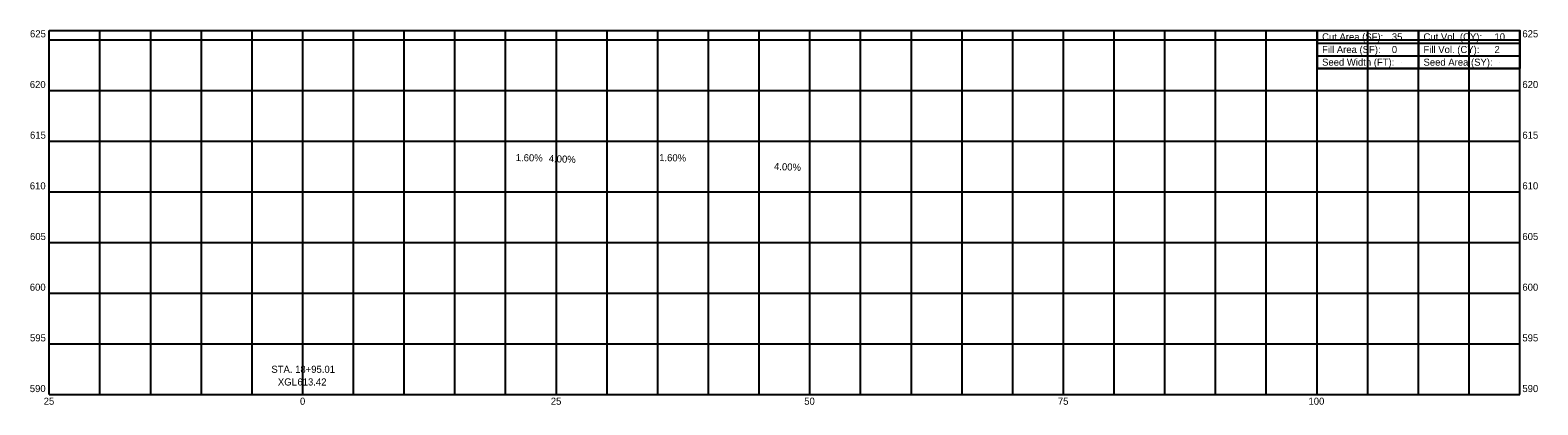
# Model space of a CAD drawing. Extents: x -27 to 122, y 589 to 626.
import ezdxf

# ---------------------------------------------------------------- set-up
doc = ezdxf.new("R2010")
doc.units = 0
for name, color, linetype in [('Default', 7, 'Continuous'), ('SH_Data', 7, 'Continuous'), ('SH_Major_Grid_Line', 7, 'Continuous'), ('SH_Masking', 7, 'Continuous'), ('SH_Text', 7, 'Continuous')]:
    doc.layers.add(name, color=color, linetype=linetype)

msp = doc.modelspace()

# ---------------------------------------------------------------- linework, layer by layer
at = {"layer": 'Default'}
msp.add_circle((120, 625.92), 0.000417, dxfattribs=at)
msp.add_circle((120, 625.92), 0.000417, dxfattribs=at)
msp.add_circle((120, 625.92), 0.000417, dxfattribs=at)
msp.add_circle((120, 625.92), 0.000417, dxfattribs=at)
msp.add_circle((120, 625.92), 0.000417, dxfattribs=at)
msp.add_circle((120, 625.92), 0.000417, dxfattribs=at)
msp.add_circle((120, 625.92), 0.000417, dxfattribs=at)
msp.add_circle((120, 625.92), 0.000417, dxfattribs=at)
msp.add_circle((120, 625.92), 0.000417, dxfattribs=at)
msp.add_circle((120, 625.92), 0.000417, dxfattribs=at)
msp.add_circle((120, 625.92), 0.000417, dxfattribs=at)
msp.add_circle((120, 625.92), 0.000417, dxfattribs=at)
at = {"layer": 'SH_Data'}
for p, q in [((100, 625.92), (120, 625.92)), ((100, 625.92), (100, 623.42)), ((110, 625.92), (110, 622.17)), ((120, 625.92), (120, 623.42)), ((100, 624.67), (120, 624.67)), ((100, 623.42), (120, 623.42)), ((108.3, 622.8), (108.3, 622.8)), ((117.95, 622.8), (117.95, 622.8))]:
    msp.add_line(p, q, dxfattribs=at)
msp.add_lwpolyline([(100, 623.42), (100, 622.17), (120, 622.17), (120, 623.42)], dxfattribs=at)
at = {"layer": 'SH_Major_Grid_Line'}
for p, q in [((-25, 625.92), (120, 625.92)), ((-25, 590), (-25, 625.92)), ((-20, 590), (-20, 625.92)), ((-15, 590), (-15, 625.92)), ((-10, 590), (-10, 625.92)), ((-5, 590), (-5, 625.92)), ((0, 590), (0, 625.92)), ((5, 590), (5, 625.92)), ((10, 590), (10, 625.92)), ((15, 590), (15, 625.92)), ((20, 590), (20, 625.92)), ((25, 590), (25, 625.92)), ((30, 590), (30, 625.92)), ((35, 590), (35, 625.92)), ((40, 590), (40, 625.92)), ((45, 590), (45, 625.92)), ((50, 590), (50, 625.92)), ((55, 590), (55, 625.92)), ((60, 590), (60, 625.92)), ((65, 590), (65, 625.92)), ((70, 590), (70, 625.92)), ((75, 590), (75, 625.92)), ((80, 590), (80, 625.92)), ((85, 590), (85, 625.92)), ((90, 590), (90, 625.92)), ((95, 590), (95, 625.92)), ((100, 590), (100, 625.92)), ((105, 590), (105, 625.92)), ((110, 590), (110, 625.92)), ((115, 590), (115, 625.92)), ((120, 590), (120, 625.92)), ((-25, 625), (120, 625)), ((-25, 620), (120, 620)), ((-25, 615), (120, 615)), ((-25, 610), (120, 610)), ((-25, 605), (120, 605)), ((-25, 600), (120, 600)), ((-25, 595), (120, 595)), ((-25, 590), (120, 590))]:
    msp.add_line(p, q, dxfattribs=at)
at = {"layer": 'SH_Masking'}
msp.add_lwpolyline([(100, 625.92), (120, 625.92), (120, 622.17), (100, 622.17)], close=True, dxfattribs=at)

# ---------------------------------------------------------------- texts
at = {"layer": 'SH_Text'}
for s, p in [('625', (-26.9, 625.25)), ('625', (120.25, 625.25)), ('Cut Area (SF):', (100.5, 624.95)), ('Fill Area (SF):', (100.5, 623.7)), ('35', (107.38, 624.95)), ('0', (107.38, 623.7)), ('Cut Vol. (CY):', (110.5, 624.95)), ('Fill Vol. (CY):', (110.5, 623.7)), ('2', (117.5, 623.7)), ('10', (117.5, 624.95)), ('Seed Width (FT):', (100.5, 622.45)), ('Seed Area (SY):', (110.5, 622.45)), ('620', (-26.92, 620.25)), ('620', (120.25, 620.25)), ('615', (-26.9, 615.25)), ('615', (120.25, 615.25)), ('610', (-26.92, 610.25)), ('610', (120.25, 610.25)), ('605', (-26.9, 605.25)), ('605', (120.25, 605.25)), ('600', (-26.92, 600.25)), ('600', (120.25, 600.25)), ('595', (-26.9, 595.25)), ('595', (120.25, 595.25)), ('STA. 18+95.01', (-3.1, 592.15)), ('590', (-26.92, 590.25)), ('XGL ', (-2.46, 590.9)), ('613.42', (-0.53, 590.9)), ('590', (120.25, 590.25)), ('25', (-25.55, 589)), ('0', (-0.28, 589)), ('25', (24.45, 589)), ('50', (49.44, 589)), ('75', (74.45, 589)), ('100', (99.16, 589))]:
    msp.add_text(s, height=0.7, dxfattribs=at).set_placement(p)
for s, rotation, p in [('1.60%', 359.0833, (20.99, 613.04)), ('4.00%', 357.7094, (24.24, 612.95)), ('1.60%', 359.0833, (35.13, 613.04)), ('4.00%', 357.7094, (46.45, 612.17))]:
    msp.add_text(s, height=0.7, rotation=rotation, dxfattribs=at).set_placement(p)

doc.saveas('drawing.dxf')
